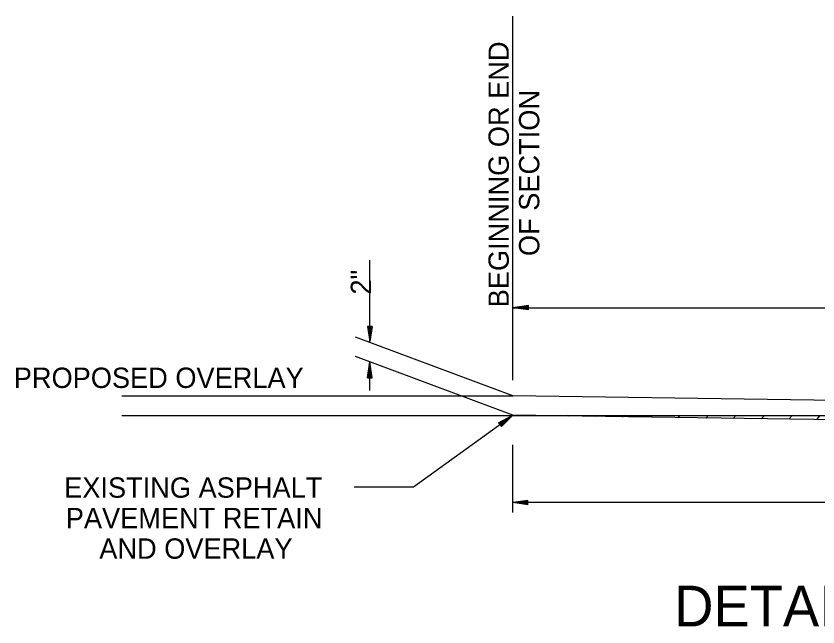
# Model space of a CAD drawing. Extents: x -2842 to 2681, y -2139 to 474.
# Drawn here: x -615.8 to -379, y -1349.9 to -1169.6 of the extents above; entities that cross this region are included whole.
import ezdxf

# ---------------------------------------------------------------- set-up
doc = ezdxf.new("R2010")
doc.units = 0
doc.layers.add('Default', color=7, linetype='Continuous')

msp = doc.modelspace()

# ---------------------------------------------------------------- linework, layer by layer
at = {"layer": 'Default'}
for p, q in [((-469.1, -1277), (-469.1, -1169.58)), ((-511.3, -1265.66), (-511.3, -1241.67)), ((-464.44, -1255), (-469.11, -1255.67)), ((-464.44, -1256.33), (-464.44, -1255)), ((-469.11, -1255.67), (-57.55, -1255.67)), ((-464.44, -1256.33), (-469.11, -1255.67)), ((-464.44, -1255.22), (-468.43, -1255.67)), ((-464.44, -1256.33), (-468.43, -1255.67)), ((-464.44, -1255.22), (-467.54, -1255.67)), ((-464.44, -1256.11), (-467.54, -1255.67)), ((-464.44, -1255.44), (-466.65, -1255.67)), ((-464.44, -1256.11), (-466.65, -1255.67)), ((-464.44, -1255.44), (-465.99, -1255.67)), ((-464.44, -1255.88), (-465.99, -1255.67)), ((-464.44, -1255.67), (-465.1, -1255.67)), ((-464.44, -1255.88), (-465.1, -1255.67)), ((-511.97, -1261.21), (-511.3, -1265.66)), ((-511.97, -1261.21), (-511.3, -1265)), ((-510.63, -1261.21), (-511.97, -1261.21)), ((-511.74, -1261.21), (-511.3, -1264.1)), ((-511.74, -1261.21), (-511.3, -1263.45)), ((-511.52, -1261.21), (-511.3, -1262.55)), ((-511.52, -1261.21), (-511.3, -1261.89)), ((-510.63, -1261.21), (-511.3, -1265.66)), ((-511.08, -1261.21), (-511.3, -1262.55)), ((-510.85, -1261.21), (-511.3, -1264.1)), ((-510.85, -1261.21), (-511.3, -1265)), ((-511.08, -1261.21), (-511.3, -1263.45)), ((-511.3, -1261.21), (-511.3, -1261.89)), ((-469.11, -1281.66), (-515.51, -1264.33)), ((-469.11, -1287.42), (-515.51, -1270.1)), ((-511.97, -1276.33), (-511.3, -1271.66)), ((-511.97, -1276.33), (-511.3, -1272.33)), ((-511.74, -1276.33), (-511.3, -1273.21)), ((-511.74, -1276.33), (-511.3, -1273.87)), ((-510.63, -1276.33), (-511.3, -1271.66)), ((-511.3, -1280.1), (-511.3, -1271.66)), ((-510.85, -1276.33), (-511.3, -1272.33)), ((-510.85, -1276.33), (-511.3, -1273.21)), ((-511.08, -1276.33), (-511.3, -1273.87)), ((-511.97, -1276.33), (-510.63, -1276.33)), ((-511.52, -1276.33), (-511.3, -1274.77)), ((-511.52, -1276.33), (-511.3, -1275.66)), ((-511.08, -1276.33), (-511.3, -1274.77)), ((-511.3, -1276.33), (-511.3, -1275.66)), ((-584.58, -1281.66), (-469.1, -1281.66)), ((-57.55, -1287.42), (-469.11, -1281.66)), ((-584.58, -1287.43), (-57.54, -1287.43)), ((-498.41, -1308.52), (-469.11, -1287.42)), ((-473.32, -1289.66), (-469.11, -1287.42)), ((-473.09, -1289.66), (-469.76, -1287.87)), ((-472.44, -1290.76), (-469.11, -1287.42)), ((-472.44, -1290.54), (-469.76, -1287.87)), ((-57.78, -1293.21), (-469.11, -1287.42)), ((-452.9, -1287.65), (-452.67, -1287.42)), ((-444.79, -1287.76), (-444.45, -1287.42)), ((-436.68, -1287.88), (-436.02, -1287.42)), ((-428.37, -1287.99), (-427.78, -1287.42)), ((-420.25, -1288.11), (-419.57, -1287.42)), ((-412.14, -1288.23), (-411.36, -1287.42)), ((-404.03, -1288.33), (-403.14, -1287.42)), ((-395.74, -1288.46), (-394.7, -1287.42)), ((-387.63, -1288.56), (-386.47, -1287.42)), ((-379.31, -1288.69), (-378.26, -1287.42)), ((-473.32, -1289.66), (-472.44, -1290.76)), ((-473.09, -1289.66), (-470.43, -1288.32)), ((-473.09, -1289.87), (-471.11, -1288.77)), ((-473.09, -1289.87), (-471.54, -1289.2)), ((-472.87, -1290.09), (-472.21, -1289.66)), ((-472.87, -1290.09), (-472.21, -1289.66)), ((-472.65, -1290.54), (-470.43, -1288.32)), ((-472.65, -1290.31), (-471.11, -1288.77)), ((-472.65, -1290.31), (-471.54, -1289.2)), ((-469.11, -1316.08), (-469.11, -1296.1)), ((-515.95, -1308.52), (-498.41, -1308.52)), ((-464.64, -1312.53), (-469.11, -1313.19)), ((-464.64, -1312.53), (-469.11, -1313.19)), ((-57.78, -1313.19), (-469.11, -1313.19)), ((-464.64, -1313.86), (-469.11, -1313.19)), ((-464.64, -1313.86), (-469.11, -1313.19)), ((-464.64, -1312.53), (-468.43, -1313.19)), ((-464.64, -1312.53), (-468.43, -1313.19)), ((-464.64, -1313.63), (-468.43, -1313.19)), ((-464.64, -1313.63), (-468.43, -1313.19)), ((-464.64, -1312.74), (-467.54, -1313.19)), ((-464.64, -1312.74), (-467.54, -1313.19)), ((-464.64, -1313.63), (-467.54, -1313.19)), ((-464.64, -1313.63), (-467.54, -1313.19)), ((-464.64, -1312.74), (-466.88, -1313.19)), ((-464.64, -1312.74), (-466.88, -1313.19)), ((-464.64, -1313.41), (-466.88, -1313.19)), ((-464.64, -1313.41), (-466.88, -1313.19)), ((-464.64, -1312.98), (-465.99, -1313.19)), ((-464.64, -1312.98), (-465.99, -1313.19)), ((-464.64, -1313.41), (-465.99, -1313.19)), ((-464.64, -1313.41), (-465.99, -1313.19)), ((-464.64, -1312.98), (-465.32, -1313.19)), ((-464.64, -1312.98), (-465.32, -1313.19)), ((-464.64, -1313.19), (-465.32, -1313.19)), ((-464.64, -1313.19), (-465.32, -1313.19)), ((-464.64, -1313.86), (-464.64, -1312.53)), ((-464.64, -1313.86), (-464.64, -1312.53))]:
    msp.add_line(p, q, dxfattribs=at)

# ---------------------------------------------------------------- texts
for s, p in [('BEGINNING OR END', (-470.28, -1255.54)), ('OF SECTION', (-461.28, -1240.42)), ('2"', (-510.96, -1251.78))]:
    msp.add_text(s, height=6, rotation=90, dxfattribs=at).set_placement(p)
for s, height, p in [('PROPOSED OVERLAY', 6, (-616.46, -1279.34)), ('EXISTING ASPHALT', 6, (-601.58, -1311.74)), ('PAVEMENT RETAIN', 6, (-601.1, -1320.74)), ('AND OVERLAY', 6, (-591.21, -1329.74)), ('DETAIL FOR TRANSITIONS', 12, (-421.44, -1349.71))]:
    msp.add_text(s, height=height, dxfattribs=at).set_placement(p)

doc.saveas('drawing.dxf')
